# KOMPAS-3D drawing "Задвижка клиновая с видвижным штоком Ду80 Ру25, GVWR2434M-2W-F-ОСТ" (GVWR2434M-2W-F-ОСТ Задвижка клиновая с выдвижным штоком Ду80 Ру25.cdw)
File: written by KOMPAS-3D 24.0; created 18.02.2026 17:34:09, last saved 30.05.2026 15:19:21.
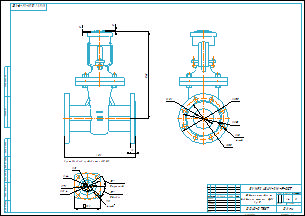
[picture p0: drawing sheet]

Document properties: Автор: R2D2; Форматы листов документа: A2; Полное имя файла: GVWR2434M-2W-F-ОСТ Задвижка клиновая с выдвижным штоком Ду80 Ру25.m3d; Масса: 24; Наименование: Задвижка клиновая с видвижным штоком Ду80 Ру25; Количество листов документа: 1; Примечание: D040-07587

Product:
- Part/product: Задвижка клиновая с видвижным штоком Ду80 Ру25  | designation GVWR2434M-2W-F-ОСТ
    Масса: 24
    Раздел спецификации: Прочие изделия
    Примечание: D040-07587

Views: Проекционный вид 2, Проекционный вид 3
Referenced files in E:\Работа\Зайцев\GVWR2121M-2W-F-ОСТ Задвижка клиновая с видвижным штоком Ду50-300 Ру16\DN80\: GVWR2121M-2W-F-ОСТ Задвижка клиновая с видвижным штоком Ду80 Ру16.m3d
Referenced files in E:\Работа\Зайцев\Для компаса\: чертеж DN.ru А3.cdt
Referenced files in E:\Работа\Зайцев\GVWR2434M-2W-F-ОСТ Задвижка клиновая с выдвижным штоком DN.ru Ду50-300 Ру25\исходные материалы\DN80\DN80\: GVWR2434M-2W-F-ОСТ Задвижка клиновая с выдвижным штоком Ду80 Ру25.m3d
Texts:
  GVWR2434M-2W-F-ОСТ
  Присоединение привода тип АК (А)
  чертеж DN.ru А3.cdt
  Задвижка клиновая с
  видвижным штоком Ду80
  Ру25
  Задвижка клиновая с видвижным штоком Ду80 Ру25
  GVWR2434M-2W-F-ОСТ Задвижка клиновая с видвижным штоком Ду80 Ру25
Dimensions and other numbers on the sheet: 0; 3; 4; 195; 135; 80; 18; 4 отв.; 160; 100; 5 кулачков; 5 впадин; 104; 70; 44; 32; 1:2; 1; 2; 24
